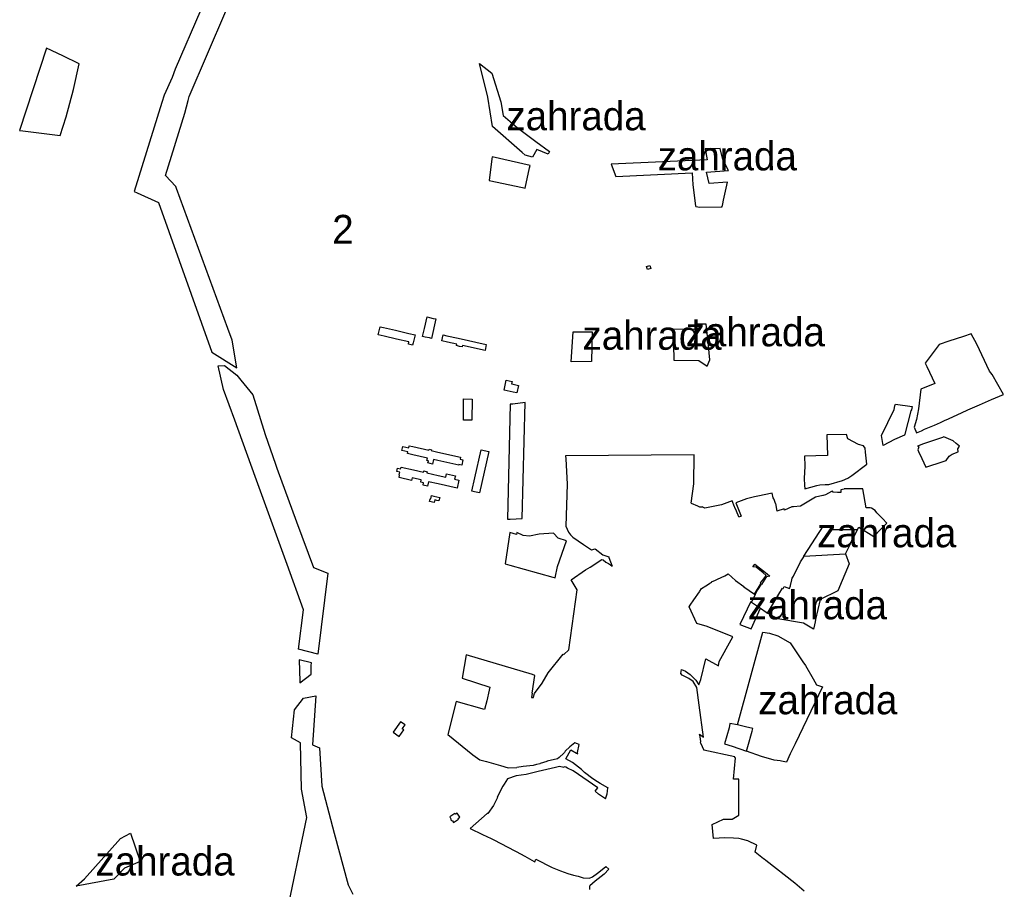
# Model space of a CAD drawing. Extents: x -800505 to -795586, y -1125317 to -1120396.
# Drawn here: x -798139 to -796773, y -1123692 to -1122485 of the extents above; entities that cross this region are included whole.
import ezdxf

# ---------------------------------------------------------------- set-up
doc = ezdxf.new("R2010")
doc.units = 0
for name, color, linetype in [('LES_ZV', 7, 'Continuous'), ('Level 255', 7, 'Continuous'), ('OVNI_SET', 7, 'Continuous'), ('TRV_POP', 7, 'Continuous'), ('TRV_ZV', 7, 'Continuous')]:
    doc.layers.add(name, color=color, linetype=linetype)

msp = doc.modelspace()

# ---------------------------------------------------------------- linework, layer by layer
at = {"layer": 'LES_ZV'}
for points in [[(-797851.9, -1122388.2), (-797923.4, -1122553.5), (-797927.3, -1122564.9), (-797938.3, -1122589.7), (-797941.7, -1122600), (-797980, -1122723.4), (-797975.9, -1122725.2), (-797946.5, -1122738.5), (-797872.3, -1122946.4), (-797837.4, -1122968.2), (-797844.1, -1122929.7), (-797850, -1122913.6), (-797921.3, -1122719.1), (-797922.2, -1122716.6), (-797936.5, -1122701.2), (-797909.7, -1122614.7), (-797905.3, -1122597), (-797904, -1122591.6), (-797802, -1122354.2)], [(-798101.8, -1122524.2), (-798139.2, -1122638.6), (-798135, -1122639.1), (-798083.1, -1122645.6), (-798074.8, -1122619.9), (-798064.5, -1122581.9), (-798056.4, -1122546.1), (-798079.1, -1122535.2), (-798101.8, -1122524.2)], [(-797483, -1122675.3), (-797483.4, -1122677.9), (-797487.1, -1122707.9), (-797440.9, -1122717.7), (-797436.9, -1122718.5), (-797430.9, -1122690.5), (-797430.2, -1122687.4), (-797483, -1122675.3)], [(-797854.8, -1122965), (-797837.4, -1122978.3), (-797831.8, -1122985.2), (-797815.4, -1123005.4), (-797798.4, -1123060.4), (-797784, -1123101.8), (-797782.1, -1123107.5), (-797754.8, -1123181.7), (-797731.3, -1123245.4), (-797711.1, -1123253.2), (-797725.3, -1123365.4), (-797752.1, -1123358.6), (-797744.8, -1123303.8), (-797767.6, -1123241.1), (-797812.1, -1123118.7), (-797840.4, -1123040.9), (-797855.9, -1122998.3), (-797863.7, -1122965.1), (-797854.8, -1122965)], [(-797049.9, -1123229.5), (-796992.4, -1123226.4), (-796987.3, -1123240), (-797002.7, -1123277.7), (-797027.2, -1123289.8), (-797033.7, -1123317.4), (-797034.4, -1123320.7), (-797036.4, -1123329), (-797036.8, -1123330.9), (-797050.5, -1123322.4), (-797086.3, -1123316.4), (-797100.6, -1123308.5)], [(-797750.9, -1123373.2), (-797750, -1123403.4), (-797749.9, -1123405.2), (-797734.5, -1123393.1), (-797734.4, -1123389.7), (-797734.2, -1123381.1), (-797734.1, -1123377.4), (-797750.9, -1123373.2)], [(-797757.7, -1123442.9), (-797745.1, -1123426.4), (-797727.7, -1123423.5), (-797732.7, -1123491.2), (-797722.7, -1123495.5), (-797719.7, -1123548.9), (-797702.3, -1123613.8), (-797683, -1123685.7), (-797676.4, -1123698.6)], [(-797769.6, -1123731.8), (-797740.2, -1123592.4), (-797748, -1123552.7), (-797749.3, -1123488.7), (-797761.6, -1123481.7), (-797757.7, -1123442.9)]]:
    msp.add_lwpolyline(points, dxfattribs=at)
at = {"layer": 'Level 255'}
for points in [[(-797263.8, -1122826.1), (-797262.5, -1122830.3), (-797267.1, -1122831.8), (-797268.5, -1122827.6), (-797263.8, -1122826.1)], [(-797573.4, -1122897.4), (-797570.2, -1122898.2), (-797564.8, -1122899.4), (-797561.8, -1122900), (-797561.3, -1122900.2), (-797567.4, -1122927.2), (-797570.1, -1122926.6), (-797575.8, -1122925.3), (-797579.5, -1122924.5), (-797577, -1122913.5), (-797573.4, -1122897.4)], [(-797638.6, -1122911.1), (-797634.1, -1122912.1), (-797617.1, -1122916), (-797598.8, -1122920.2), (-797590.1, -1122922.1), (-797592.6, -1122933.4), (-797593.4, -1122936.8), (-797597.1, -1122935.9), (-797599.3, -1122935.4), (-797598.6, -1122932.1), (-797615.9, -1122928.1), (-797632.9, -1122924.3), (-797641.2, -1122922.4), (-797638.6, -1122911.1)], [(-797551.1, -1122922.3), (-797545.9, -1122923.5), (-797530.1, -1122927), (-797491.1, -1122935.8), (-797492.9, -1122944), (-797524, -1122937), (-797524.5, -1122939.1), (-797528.4, -1122938.3), (-797532.5, -1122937.3), (-797532, -1122935.2), (-797544.9, -1122932.3), (-797552.9, -1122930.5), (-797551.1, -1122922.3)], [(-797463.3, -1122985.1), (-797455.3, -1122986.9), (-797456.1, -1122990.2), (-797453.6, -1122990.8), (-797446.2, -1122992.4), (-797448.6, -1123003), (-797453.9, -1123001.8), (-797466.4, -1122999), (-797463.3, -1122985.1)], [(-797522.8, -1123011.3), (-797510.8, -1123011.4), (-797511, -1123040.6), (-797523, -1123040.5), (-797522.8, -1123011.3)], [(-797598.2, -1123076.2), (-797593, -1123077.4), (-797570.8, -1123082.3), (-797570.5, -1123081.1), (-797567.4, -1123081.8), (-797567.6, -1123083), (-797558.2, -1123085.1), (-797527, -1123092.1), (-797527.6, -1123094.9), (-797523.5, -1123095.8), (-797525.2, -1123103.4), (-797529.3, -1123102.4), (-797529.4, -1123103), (-797558.2, -1123096.6), (-797564.5, -1123095.2), (-797565.8, -1123101.6), (-797572.2, -1123100.1), (-797571.5, -1123097), (-797573.7, -1123096.5), (-797572.9, -1123093.4), (-797593, -1123088.9), (-797600.7, -1123087.2), (-797600.1, -1123084.5), (-797608.3, -1123082.6), (-797607.1, -1123077.1), (-797598.8, -1123078.9), (-797598.2, -1123076.2)], [(-797498.3, -1123082), (-797487.6, -1123084.4), (-797500.7, -1123141.7), (-797507.4, -1123140.1), (-797511.3, -1123139.2), (-797507.2, -1123120.8), (-797498.3, -1123082)], [(-797609.5, -1123105.8), (-797592.4, -1123109.7), (-797578.1, -1123112.9), (-797577.7, -1123111.2), (-797573.3, -1123112.2), (-797573.7, -1123113.9), (-797558.1, -1123117.5), (-797547.5, -1123119.9), (-797546.3, -1123115.1), (-797534.1, -1123117.8), (-797535.2, -1123122.7), (-797529.2, -1123124.1), (-797531.8, -1123135.1), (-797558, -1123129.1), (-797571.2, -1123126.1), (-797572.6, -1123132.3), (-797578.8, -1123130.9), (-797578.1, -1123127.9), (-797582.2, -1123126.9), (-797581.5, -1123123.7), (-797592.2, -1123121.3), (-797594.1, -1123120.9), (-797594.8, -1123124.3), (-797612.3, -1123120.2), (-797611.6, -1123116.9), (-797612.1, -1123116.8), (-797611.2, -1123112.9), (-797615.4, -1123111.9), (-797614.3, -1123107.3), (-797610.1, -1123108.2), (-797609.5, -1123105.8)], [(-797567.1, -1123145.4), (-797563.8, -1123146.2), (-797559.8, -1123147.2), (-797555.8, -1123148.2), (-797556.9, -1123152.7), (-797559.9, -1123152), (-797562.8, -1123151.3), (-797563.7, -1123154.9), (-797569.8, -1123153.4), (-797568.9, -1123149.8), (-797568.2, -1123149.9), (-797567.1, -1123145.4)]]:
    msp.add_lwpolyline(points, dxfattribs=at)
at = {"layer": 'OVNI_SET'}
for p, q in [((-797144.7, -1123155.5), (-797137.2, -1123173.8)), ((-797089.5, -1123156.4), (-797087.5, -1123167.2)), ((-797140.5, -1123175), (-797137.2, -1123173.8)), ((-797120.8, -1123244.1), (-797118, -1123240.7)), ((-797193.7, -1123488.4), (-797188.8, -1123498.7)), ((-797325.2, -1123660), (-797320.8, -1123664))]:
    msp.add_line(p, q, dxfattribs=at)
for points in [[(-796893.6, -1123039.6), (-796896.7, -1123050.6), (-796893.4, -1123058.3), (-796886.9, -1123055.3), (-796882.5, -1123053.2), (-796868.5, -1123047.6), (-796860.3, -1123043.8), (-796854.7, -1123041.2), (-796849.1, -1123038.7), (-796842.1, -1123035.5), (-796831, -1123030.4), (-796822.2, -1123026.6), (-796806, -1123019.5), (-796789.3, -1123012.2), (-796773, -1123004.9), (-796788.6, -1122977.5), (-796792.2, -1122972.7), (-796810, -1122935.4), (-796817.6, -1122921.1), (-796828.3, -1122924.5), (-796848.5, -1122931.3), (-796862.1, -1122935.8)], [(-796862.1, -1122935.8), (-796869.2, -1122945.1), (-796881.5, -1122961.4), (-796879.4, -1122966.3), (-796868.2, -1122989.6), (-796887.8, -1122997.8), (-796890.7, -1123025), (-796893.6, -1123039.6)], [(-797457.9, -1123018.6), (-797461.7, -1123177.9), (-797458, -1123178.2), (-797441.1, -1123177.3), (-797437.2, -1123016.4), (-797454.3, -1123018.4), (-797457, -1123018.6), (-797457.9, -1123018.6)], [(-796922.9, -1123018.5), (-796899.6, -1123021.8), (-796900.7, -1123026.3), (-796901.3, -1123027.9), (-796909.7, -1123060.2), (-796910.1, -1123061.4), (-796924, -1123067.7), (-796939.8, -1123075.9), (-796942.2, -1123062.2), (-796924.6, -1123025.7), (-796923.5, -1123021), (-796922.9, -1123018.5)], [(-797048.9, -1123136.2), (-797032, -1123131.5), (-797028, -1123130.4), (-797020.4, -1123130.2), (-797015.7, -1123130.1), (-797015.6, -1123130.2), (-796996.4, -1123124.6), (-796989, -1123121), (-796983.6, -1123117.4), (-796962.8, -1123101.7), (-796964.3, -1123085.1), (-796964.8, -1123079.8), (-796967.3, -1123076.2), (-796974.1, -1123074.5), (-796989.1, -1123066.7), (-796990.8, -1123060.7), (-797018.3, -1123061.2), (-797017.4, -1123089.6), (-797033.4, -1123090.1), (-797049.4, -1123090.6), (-797048.9, -1123104.6), (-797049.5, -1123121.8), (-797049.3, -1123131), (-797049.1, -1123131), (-797048.9, -1123136.2)], [(-796892.4, -1123076.7), (-796890.2, -1123077.8), (-796891.7, -1123081.8), (-796890.7, -1123084.1), (-796886.3, -1123094.1), (-796883.5, -1123099.9), (-796880.7, -1123105.8), (-796873.6, -1123103.5), (-796863.7, -1123100.4), (-796853.8, -1123097.2), (-796852.2, -1123096.7), (-796848.3, -1123090.8), (-796843.9, -1123087.9), (-796835.8, -1123084.8), (-796836.1, -1123080.5), (-796833.7, -1123076.6), (-796838.3, -1123072.9), (-796842.8, -1123069.4), (-796855.5, -1123063.9), (-796857.7, -1123064.7), (-796884.1, -1123073.7), (-796892.4, -1123076.7)], [(-797206.4, -1123156.1), (-797202.7, -1123129), (-797202.4, -1123088.9), (-797380.9, -1123090.1), (-797380.7, -1123094.2), (-797380.2, -1123103.2), (-797378.7, -1123129.5), (-797380.8, -1123187.9), (-797376.9, -1123196.2), (-797374.3, -1123199.9), (-797371.1, -1123203.1), (-797356.3, -1123213.5), (-797345, -1123220.8), (-797340.1, -1123219.3), (-797329.1, -1123227.7), (-797321, -1123230.4), (-797320.8, -1123230.5)], [(-797089.5, -1123156.4), (-797091.1, -1123151), (-797091.8, -1123149.7), (-797092.6, -1123148.4), (-797094.1, -1123142), (-797114.2, -1123146.1), (-797118.6, -1123147), (-797129.9, -1123149.7), (-797144.7, -1123155.5)], [(-796935, -1123183.5), (-796940.8, -1123177.1), (-796948.5, -1123169.1), (-796950.9, -1123166.1), (-796956.2, -1123162.8), (-796958.1, -1123162.6), (-796963.6, -1123162.2), (-796968.3, -1123136.1), (-796981.6, -1123135.9), (-796994, -1123135.9), (-796994, -1123136.4), (-796998.5, -1123137.2), (-796998.7, -1123141.3), (-797003.4, -1123141.1), (-797010, -1123140.8), (-797009.9, -1123139.4), (-797011.5, -1123139.8), (-797020, -1123144.2), (-797023.4, -1123145.4), (-797023.8, -1123145.5), (-797033.9, -1123147.7), (-797054.6, -1123159.9), (-797064.5, -1123160.8), (-797066.8, -1123161.1), (-797076.8, -1123165.8), (-797077.5, -1123163.8), (-797087.5, -1123167.2)], [(-797206.4, -1123156.1), (-797198, -1123159.6), (-797195, -1123160.8), (-797191.2, -1123161.2)], [(-797140.5, -1123175), (-797143.4, -1123167.2), (-797146, -1123161.7), (-797146.3, -1123161), (-797149.6, -1123152.6), (-797164.6, -1123158.3), (-797187.8, -1123162.8), (-797191.2, -1123161.2)], [(-797118, -1123240.7), (-797101.2, -1123253.9), (-797097.5, -1123257.2), (-797101.4, -1123258.1), (-797101.8, -1123257.9), (-797108.9, -1123268.8), (-797109.5, -1123268.5), (-797114.3, -1123276.1), (-797117.9, -1123282.7), (-797122.7, -1123293.3), (-797110.4, -1123301.8), (-797102.6, -1123307.4), (-797100.6, -1123308.5), (-797084.8, -1123282.4), (-797079.5, -1123273.7), (-797078.6, -1123274.3), (-797077.2, -1123271.4), (-797069.8, -1123274.4), (-797068.4, -1123270.6), (-797068.5, -1123270.3), (-797066.7, -1123262.4), (-797066.1, -1123260), (-797064.6, -1123257.1), (-797054.8, -1123237.2), (-797050.3, -1123230.4), (-797049.9, -1123229.5), (-797023, -1123187.2), (-797011.6, -1123187.1), (-797012, -1123192.5), (-796975.5, -1123192.5), (-796973.6, -1123189.3), (-796953, -1123202.3), (-796943.7, -1123192.6), (-796935, -1123183.5)], [(-797449.2, -1123199.4), (-797458.2, -1123196.6), (-797464.7, -1123239.9), (-797458.5, -1123241.8), (-797398.7, -1123258.5), (-797395.5, -1123259.4), (-797392.3, -1123244), (-797379.8, -1123208.2), (-797391.4, -1123204.4), (-797397.8, -1123197.7), (-797417.7, -1123199), (-797430.9, -1123201.7), (-797439.7, -1123200.6), (-797448.8, -1123196.4), (-797449.2, -1123199.4)], [(-797413.7, -1123405.7), (-797405, -1123391.6), (-797384.3, -1123365.7), (-797383.3, -1123365.8), (-797376.5, -1123359.6), (-797365, -1123276.1), (-797373.3, -1123262.4), (-797353.4, -1123248.4), (-797346.7, -1123244.7), (-797330.5, -1123234), (-797329, -1123234.7), (-797325.2, -1123237.8), (-797321.2, -1123239.7), (-797318.4, -1123241.4), (-797316.5, -1123243.2)], [(-797320.8, -1123230.5), (-797321, -1123231.3), (-797316.5, -1123243.2)], [(-797193.7, -1123488.4), (-797193.3, -1123486.7), (-797194.3, -1123480.1), (-797195.2, -1123476.6), (-797189.4, -1123480.8), (-797195.3, -1123436.2), (-797198.7, -1123411.8), (-797203.9, -1123403.4), (-797209.8, -1123399.3), (-797219.2, -1123394.7), (-797221.1, -1123392.3), (-797220.2, -1123386.6), (-797214.6, -1123389.1), (-797207.9, -1123393.5), (-797199.9, -1123401.7), (-797195.7, -1123408.2), (-797193, -1123400.8), (-797186.1, -1123372.1), (-797168.8, -1123381.5), (-797167.8, -1123375.6), (-797150.9, -1123345.5), (-797148.7, -1123341.6), (-797184.3, -1123327), (-797198.8, -1123323.1), (-797209.4, -1123299.6), (-797207.8, -1123297.6), (-797202.9, -1123290.3), (-797195.2, -1123279.1), (-797194.4, -1123277.9), (-797192.2, -1123274.5), (-797186.4, -1123270.8), (-797182.4, -1123268.2), (-797180.5, -1123267), (-797178.1, -1123265.4), (-797178.3, -1123265.1), (-797172.9, -1123262.6), (-797169.9, -1123261.3), (-797159.8, -1123256.6), (-797155.2, -1123253.8), (-797144.8, -1123263.1), (-797133.5, -1123271.6), (-797133.3, -1123271.9), (-797118.7, -1123282.3), (-797109.4, -1123266.8), (-797110.1, -1123266.4), (-797105.7, -1123261.1), (-797102.3, -1123256.4), (-797106.5, -1123252.7), (-797116.4, -1123244.6), (-797120.8, -1123244.1)], [(-797426.8, -1123393.9), (-797519.2, -1123366.4), (-797524.5, -1123398.9), (-797486, -1123411.4), (-797486.9, -1123415.3), (-797490.6, -1123430.3), (-797493.5, -1123442.5), (-797532.8, -1123431.1), (-797544.5, -1123477.1), (-797509.8, -1123505.4), (-797499.9, -1123512.3), (-797491, -1123514.6), (-797471.6, -1123519.9)], [(-797427.6, -1123419.6), (-797428.5, -1123425.5), (-797425.7, -1123425.6), (-797424.8, -1123421.5), (-797424.1, -1123420.2), (-797413.7, -1123405.7)], [(-797427.6, -1123419.6), (-797423.6, -1123394.9), (-797426.8, -1123393.9)], [(-797610.1, -1123459.2), (-797620.5, -1123473.9), (-797612.3, -1123479.7), (-797605.8, -1123470.6), (-797607.9, -1123469.1), (-797604, -1123463.6), (-797610.1, -1123459.2)], [(-797153.1, -1123461.5), (-797153.8, -1123467.7), (-797160.1, -1123489.8), (-797149.5, -1123493.2), (-797129.6, -1123500.3), (-797127.7, -1123493.5), (-797121.7, -1123472.2), (-797120.9, -1123468.7), (-797131.3, -1123466.3), (-797142.4, -1123463.7), (-797153.1, -1123461.5)], [(-797322.4, -1123550.7), (-797322.5, -1123550.9), (-797333, -1123545.1), (-797336.7, -1123542.7), (-797343.1, -1123538.4), (-797354.7, -1123529.5), (-797358.9, -1123525.7), (-797371.6, -1123515.7), (-797380.5, -1123510.7), (-797373.9, -1123498.2), (-797366, -1123502.8), (-797364.2, -1123503.6), (-797364.5, -1123502.1), (-797361.9, -1123491), (-797364.5, -1123490), (-797368.1, -1123488.4), (-797374.9, -1123494.2), (-797381.5, -1123500.1), (-797382.7, -1123501.9), (-797383.5, -1123502.8), (-797389.8, -1123508.9), (-797392, -1123510.6), (-797402.5, -1123512.9), (-797407, -1123513.9), (-797406.9, -1123514.6), (-797411.5, -1123515.9), (-797416.5, -1123517.4), (-797416.9, -1123517.5), (-797420.7, -1123518.5), (-797421.6, -1123518.7), (-797426.1, -1123519.8), (-797440.1, -1123521.5), (-797448.6, -1123522.8)], [(-797062.7, -1123683.2), (-797102.7, -1123652), (-797103.9, -1123651), (-797106, -1123649.4), (-797117.8, -1123640.2), (-797115.5, -1123630.4), (-797127.8, -1123624.6), (-797136.6, -1123622.3), (-797140.5, -1123621.2), (-797147.8, -1123620.8), (-797159.6, -1123620.2), (-797175.5, -1123621.1), (-797177.4, -1123601.8), (-797161.8, -1123594.4), (-797149.8, -1123594.5), (-797140.3, -1123588.8), (-797140.6, -1123539.2), (-797147.6, -1123538.8), (-797145, -1123509.4), (-797146.1, -1123509), (-797146, -1123507.8), (-797188.8, -1123498.7)], [(-797336.2, -1123551.2), (-797370.6, -1123527.5), (-797378.2, -1123523.6), (-797380.7, -1123522.4), (-797383, -1123521.7), (-797383.2, -1123523), (-797389.4, -1123521.6), (-797394.9, -1123522.9), (-797419.3, -1123528.4), (-797435.8, -1123532.4), (-797449.7, -1123534.4), (-797461.6, -1123538.4), (-797466.4, -1123545.7), (-797468.2, -1123548.6), (-797476.2, -1123564), (-797475.6, -1123564.3), (-797481.1, -1123575.3), (-797489.2, -1123586.7), (-797489.7, -1123586.8), (-797513.4, -1123607.5), (-797496.3, -1123615.6), (-797484.5, -1123621.3), (-797480.6, -1123623.2), (-797451.3, -1123638.3), (-797449.5, -1123639.3), (-797437.4, -1123646), (-797434.5, -1123647.7), (-797424.5, -1123653.2), (-797423.6, -1123653.8), (-797422.4, -1123650.1), (-797399.8, -1123661.7), (-797388.2, -1123666.3), (-797377.8, -1123669.8), (-797369.9, -1123672.2), (-797363.5, -1123673.7), (-797356.8, -1123675.8), (-797347.8, -1123676.6), (-797343.5, -1123674.5), (-797336.7, -1123669.6), (-797330.1, -1123664.2), (-797325.2, -1123660)], [(-797471.6, -1123519.9), (-797460.7, -1123523.3), (-797448.6, -1123522.8)], [(-797325.7, -1123566.3), (-797335.2, -1123559.9), (-797339.8, -1123555.8), (-797336.2, -1123551.2)], [(-797325.7, -1123566.3), (-797323.1, -1123559.3), (-797322.8, -1123555.6), (-797322.5, -1123550.9)], [(-797534.8, -1123586.6), (-797541.9, -1123591.4), (-797540.2, -1123593.9), (-797540.4, -1123595.2), (-797539.6, -1123596.4), (-797538.2, -1123596.8), (-797536.5, -1123599.3), (-797529.5, -1123594.5), (-797530.2, -1123593.4), (-797527.7, -1123591.7), (-797531.6, -1123586), (-797534.1, -1123587.7), (-797534.8, -1123586.6)], [(-797320.8, -1123664), (-797327.4, -1123670.8), (-797339.9, -1123680.4), (-797347.1, -1123686.9), (-797347.7, -1123688.1), (-797347.9, -1123692.1)], [(-797049.8, -1123694.6), (-797062.7, -1123683.2)]]:
    msp.add_lwpolyline(points, dxfattribs=at)
at = {"layer": 'TRV_ZV'}
for points in [[(-797500.7, -1122545.7), (-797483.2, -1122559.3), (-797470.8, -1122598.7), (-797467.8, -1122617.9), (-797448.2, -1122634.5), (-797422.5, -1122653.8), (-797403.4, -1122667.9), (-797405.3, -1122671.6), (-797420.8, -1122665.1), (-797427.1, -1122675.7), (-797437.1, -1122672.9), (-797441.3, -1122669.2), (-797482.4, -1122633.3), (-797489, -1122592.6), (-797500.7, -1122545.7)], [(-797317.8, -1122685.4), (-797311.2, -1122702.6), (-797205.2, -1122697.4), (-797204.1, -1122713.9), (-797200.4, -1122743.4), (-797200.3, -1122744.2), (-797194.5, -1122745.1), (-797164.9, -1122744.6), (-797163.7, -1122744.5), (-797162.7, -1122740.3), (-797161.6, -1122735.2), (-797156.3, -1122710.3), (-797181.7, -1122712.1), (-797185.1, -1122696.3), (-797154.9, -1122694), (-797162.8, -1122678.8), (-797166.4, -1122663.5), (-797187.2, -1122664.2), (-797184.3, -1122679.2), (-797317.8, -1122685.4)], [(-797231.7, -1122914.5), (-797230.7, -1122957.6), (-797195.8, -1122957.7), (-797184.2, -1122965.6), (-797180.5, -1122957.1), (-797183.1, -1122932.4), (-797185.6, -1122907.6), (-797198.9, -1122907.3), (-797198.5, -1122914.8), (-797231.7, -1122914.5)], [(-797370.3, -1122917.9), (-797344.3, -1122917.9), (-797345.2, -1122959.5), (-797373.3, -1122959.8), (-797370.3, -1122917.9)], [(-796992.4, -1123226.4), (-796978.3, -1123198.3), (-796975.5, -1123192.5)], [(-797122.7, -1123293.3), (-797123.7, -1123292.6), (-797138.8, -1123324.4), (-797123.1, -1123330.1), (-797110.4, -1123301.8)], [(-797142.4, -1123463.7), (-797107.1, -1123334.9), (-797098, -1123336.5), (-797086.4, -1123340.2), (-797068.9, -1123349.8), (-797051.4, -1123376.2), (-797048, -1123381.4), (-797037.1, -1123399.9), (-797032.3, -1123408), (-797024.4, -1123410.8), (-797062.2, -1123489.8), (-797069, -1123503.9), (-797074, -1123515.3), (-797081.1, -1123513.9), (-797083, -1123513.7), (-797091.3, -1123512.5), (-797108.8, -1123507.6), (-797129.6, -1123500.3)], [(-798060.8, -1123687.5), (-798049.3, -1123677.2), (-797999, -1123621.3), (-797985.2, -1123614.1), (-797971.7, -1123653.4), (-797993.6, -1123662.5), (-798008.6, -1123677.8), (-798060.8, -1123687.5)]]:
    msp.add_lwpolyline(points, dxfattribs=at)

# ---------------------------------------------------------------- texts
at = {"layer": 'Level 255'}
msp.add_text('2', height=40, dxfattribs=at).set_placement((-797705.1, -1122795.8))
at = {"layer": 'TRV_POP'}
for p in [(-797463.1, -1122638.4), (-797253.1, -1122694), (-797357.5, -1122943), (-797214.2, -1122938.2), (-797031.6, -1123217.1), (-797127.9, -1123317.1), (-797113.4, -1123448.9), (-798033.9, -1123672.7)]:
    msp.add_text('zahrada', height=40, dxfattribs=at).set_placement(p)

doc.saveas('drawing.dxf')
